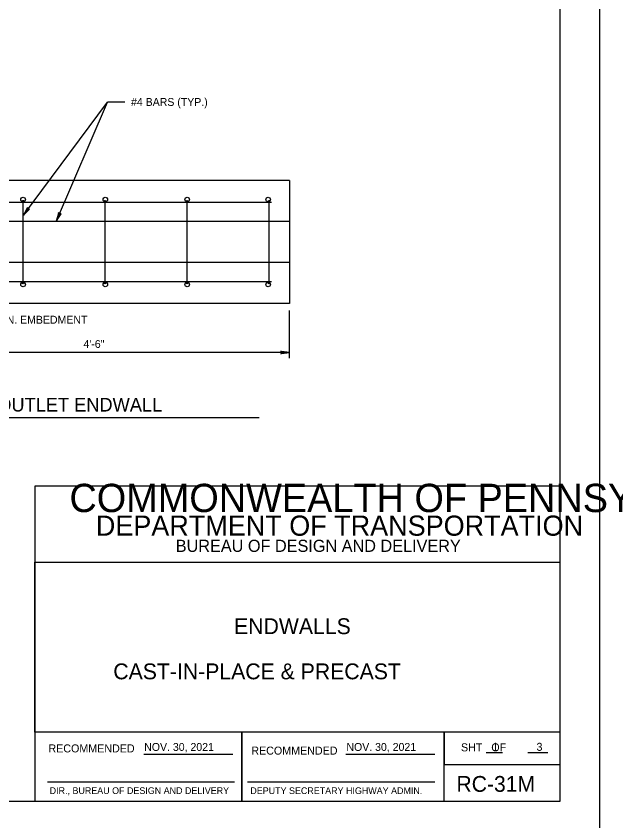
# Model space of a CAD drawing. Extents: x 638877 to 639960, y 297341 to 299123.
# Drawn here: x 639496 to 639724.4, y 298536.8 to 298843.4 of the extents above; entities that cross this region are included whole.
import ezdxf

# ---------------------------------------------------------------- set-up
doc = ezdxf.new("R2010")
doc.units = 0
for name, color, linetype in [('1', 7, 'Continuous'), ('2', 7, 'Continuous'), ('3', 7, 'Continuous'), ('PLT-BNDY', 7, 'Continuous')]:
    doc.layers.add(name, color=color, linetype=linetype)

msp = doc.modelspace()

# ---------------------------------------------------------------- linework, layer by layer
at = {"layer": '1'}
for p, q in [((639498.73, 298741.71), (639498.73, 298772.91)), ((639529.93, 298741.71), (639529.93, 298772.91)), ((639561.13, 298741.71), (639561.13, 298772.91)), ((639544.65, 298562.27), (639578.54, 298562.27)), ((639621.65, 298562.27), (639655.52, 298562.27)), ((639675.05, 298562.82), (639681.2, 298562.82)), ((639690.86, 298562.82), (639698.51, 298562.82)), ((639507.95, 298551.61), (639579.2, 298551.61)), ((639584.12, 298551.61), (639655.46, 298551.61))]:
    msp.add_line(p, q, dxfattribs=at)
msp.add_lwpolyline([(639703.19, 298544.28), (639703.19, 299108.28), (638917.19, 299108.28), (638917.19, 298544.28), (639703.19, 298544.28), (639703.19, 298570.64), (639503.19, 298570.64), (639503.19, 298635.32), (639703.19, 298635.32), (639703.19, 298664.28), (639503.19, 298664.28), (639503.19, 298544.28), (639581.99, 298544.28), (639581.99, 298570.64), (639581.99, 298544.28), (639658.99, 298544.28), (639658.99, 298570.64), (639658.99, 298558.33), (639703.19, 298558.33)], dxfattribs=at)
for centre, radius in [((639498.69, 298773.49), 0.864), ((639530.01, 298773.49), 0.864), ((639561.2, 298773.49), 0.864), ((639592, 298773.49), 0.864), ((639498.73, 298772.91), 0.289), ((639529.93, 298772.91), 0.289), ((639561.13, 298772.91), 0.289), ((639592.33, 298772.91), 0.289), ((639498.69, 298741.12), 0.864), ((639498.73, 298741.71), 0.289), ((639498.73, 298741.71), 0.289), ((639530.01, 298741.12), 0.864), ((639529.93, 298741.71), 0.289), ((639529.93, 298741.71), 0.289), ((639561.2, 298741.12), 0.864), ((639561.13, 298741.71), 0.289), ((639561.13, 298741.71), 0.289), ((639592, 298741.12), 0.864), ((639592.33, 298741.71), 0.289), ((639592.33, 298741.71), 0.289)]:
    msp.add_circle(centre, radius, dxfattribs=at)
at = {"layer": '2'}
for p, q in [((639498.86, 298767.58), (639530.84, 298810.63)), ((639511.43, 298765.34), (639530.84, 298810.63)), ((639600.13, 298780.71), (639459.73, 298780.71)), ((639600.13, 298780.71), (639600.13, 298733.91)), ((639593.28, 298772.42), (639466.82, 298772.42)), ((639592.33, 298772.91), (639592.33, 298741.71)), ((639600.13, 298765.11), (639459.73, 298765.11)), ((639600.13, 298749.51), (639459.73, 298749.51)), ((639593.28, 298742.19), (639466.82, 298742.19)), ((639600.13, 298733.91), (639459.73, 298733.91)), ((639600.13, 298713.09), (639600.13, 298731.25)), ((639600.13, 298715.23), (639459.73, 298715.23))]:
    msp.add_line(p, q, dxfattribs=at)
for points in [[(639500.38, 298770.27), (639500.49, 298770.05), (639498.86, 298767.58), (639500.38, 298770.27), (639500.37, 298770.48), (639498.86, 298767.58), (639500.73, 298769.86), (639500.98, 298769.82), (639498.86, 298767.58), (639501.19, 298769.87), (639500.98, 298769.82)], [(639512.29, 298768.32), (639512.45, 298768.12), (639511.43, 298765.34), (639512.29, 298768.32), (639512.23, 298768.52), (639511.43, 298765.34), (639512.73, 298768), (639512.98, 298768.02), (639511.43, 298765.34), (639513.18, 298768.11), (639512.98, 298768.02)]]:
    msp.add_lwpolyline(points, dxfattribs=at)
at = {"layer": '3'}
for p, q in [((639537.5, 298810.63), (639530.84, 298810.63)), ((639375.71, 298690.46), (639588.62, 298690.46))]:
    msp.add_line(p, q, dxfattribs=at)
msp.add_lwpolyline([(639597.06, 298715.62), (639597.17, 298715.4), (639600.13, 298715.23), (639597.06, 298715.62), (639596.9, 298715.75), (639600.13, 298715.23), (639597.17, 298715.09), (639597.07, 298714.87), (639600.13, 298715.23), (639596.9, 298714.72), (639597.07, 298714.87)], dxfattribs=at)
at = {"layer": 'PLT-BNDY'}
msp.add_lwpolyline([(638877.19, 299123.28), (639718.19, 299123.28), (639718.19, 298529.28), (638877.19, 298529.28)], close=True, dxfattribs=at)

# ---------------------------------------------------------------- texts
at = {"layer": '1'}
for s, height, p in [('COMMONWEALTH OF PENNSYLVANIA', 10.7834, (639516.34, 298654.43)), ('DEPARTMENT OF TRANSPORTATION', 7.6843, (639526.4, 298645.43)), ('BUREAU OF DESIGN AND DELIVERY', 4.6221, (639556.83, 298639.27)), ('ENDWALLS', 6.04, (639579.04, 298607.94)), ('CAST-IN-PLACE & PRECAST', 6.04, (639533.05, 298590.73)), ('RECOMMENDED', 3.048, (639508.35, 298562.88)), ('NOV. 30, 2021', 3, (639544.82, 298563.45)), ('NOV. 30, 2021', 3, (639621.82, 298563.45)), ('SHT   OF', 3.048, (639665.44, 298563.28)), ('APPROVED', 0.0192, (639546.21, 298562.22)), ('RECOMMENDED', 3.048, (639585.6, 298562.04)), ('RC-31M', 6.016, (639663.72, 298547.87)), ('DIR., BUREAU OF DESIGN AND DELIVERY', 2.54, (639508.82, 298547.05)), ('DEPUTY SECRETARY HIGHWAY ADMIN.', 2.54, (639585.23, 298547.02))]:
    msp.add_text(s, height=height, dxfattribs=at).set_placement(p)
at = {"layer": '2'}
for s, p in [('1', (639677.39, 298563.49)), ('3', (639694.21, 298563.47))]:
    msp.add_text(s, height=3.05, dxfattribs=at).set_placement(p)
at = {"layer": '3'}
for s, height, p in [('#4 BARS (TYP.)', 2.9999, (639539.8, 298809.18)), ('3" MIN. EMBEDMENT', 2.9999, (639483.21, 298726.22)), ('4\'-6"', 3, (639521.68, 298716.98)), ('(PRECAST) SUBSURFACE DRAIN OUTLET ENDWALL', 5.1858, (639376.74, 298692.75))]:
    msp.add_text(s, height=height, dxfattribs=at).set_placement(p)

doc.saveas('drawing.dxf')
